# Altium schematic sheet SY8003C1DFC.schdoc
size 127 x 101 mm
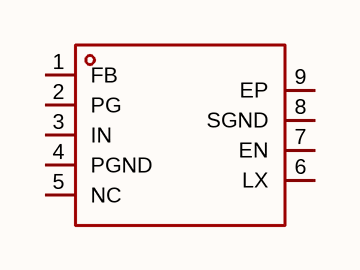
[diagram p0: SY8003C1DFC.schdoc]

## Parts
U?  sy8003c1dfc  [WDFN-8_L2.0-W2.0-P0.50-BL-EP]  (value not drawn)

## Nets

Not connected (* = marked no-connect by the designer): U? 1(FB) 2(PG) 3(IN) 4(PGND) 5(NC) 6(LX) 7(EN) 8(SGND) 9(EP)

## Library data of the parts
U? = sy8003c1dfc: 功能类型:降压型;工作电压:2.7V~5.5V;输出电压:-;输出电流:3A;输出类型:可调;; Manufacturer: Silergy(矽力杰); AddInBom: yes; ModelId: 5d21199983284a53a818bcd616561d7c; ModelName: WDFN-8_L2.0-W2.0-H0.8-P0.50; ModelTransform: 78.74,77.96,0,90,0,0,0,0,0; Function: 降压型; Output Current: 3A; Frequency - Switching: 3MHz; Synchronous Rectifier: 是; Number of Outputs: 1; Topology: 降压式; Quiescent Current: 55uA; Switch tube (built-in/external): 内置; Output Type: 可调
